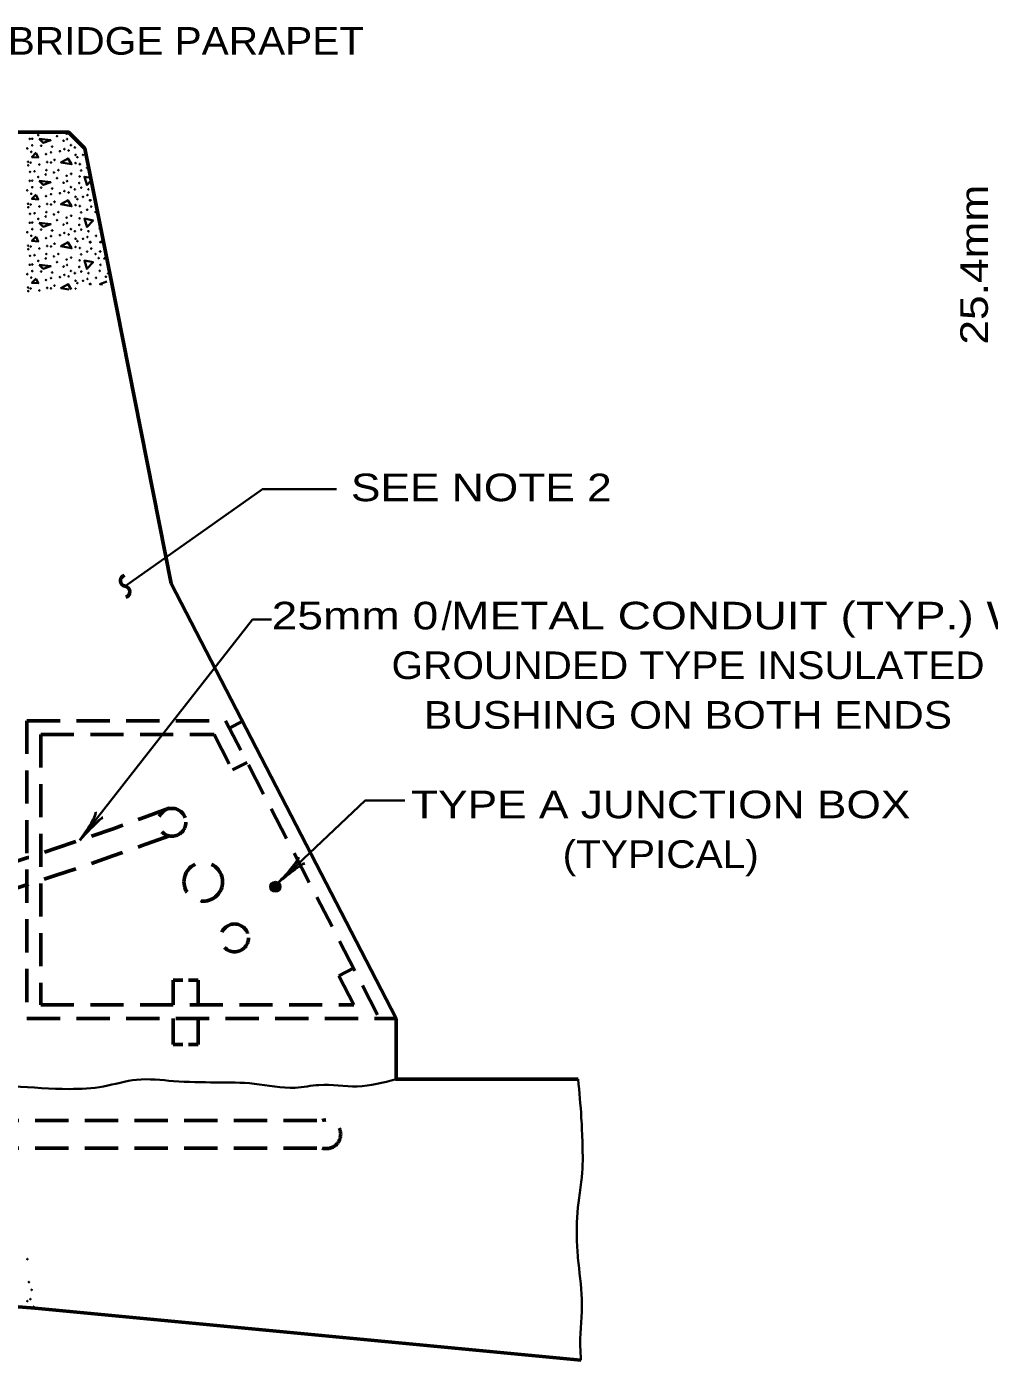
# Model space of a CAD drawing. Extents: x -35 to 821, y -23 to 522.
# Drawn here: x 406.3 to 511, y 94.3 to 239.3 of the extents above; entities that cross this region are included whole.
import ezdxf
from ezdxf.enums import TextEntityAlignment as Align

# ---------------------------------------------------------------- set-up
doc = ezdxf.new("R2010")
doc.units = 0
doc.header["$LTSCALE"] = 1.2
doc.linetypes.add('MEDIUM_DASHED', pattern=[4.5, 3, -1.5])
doc.layers.add('1', color=7, linetype='Continuous', lineweight=35)

msp = doc.modelspace()

# ---------------------------------------------------------------- hatches: boundary and pattern name
at = {"layer": '1'}
msp.add_hatch(color=256, dxfattribs=at).paths.add_polyline_path([(433.954, 145.752, 1), (432.754, 145.752, 1)])

# ---------------------------------------------------------------- linework, layer by layer
for p, q in [((413.331, 222.565), (412.859, 222.059)), ((411.148, 210.72), (410.771, 211.307)), ((406.92, 99.932), (406.947, 100.125)), ((406.995, 100.101), (407.181, 99.995))]:
    msp.add_line(p, q, dxfattribs=at)
at = {"layer": '1', "lineweight": 53}
for p, q in [((415.449, 211.896), (422.033, 178.739)), ((422.033, 178.739), (446.485, 131.414)), ((428.358, 163.014), (429.778, 163.748)), ((428.686, 158.456), (430.286, 159.283)), ((440.254, 136.068), (441.853, 136.894)), ((422.245, 132.914), (422.245, 135.614)), ((422.245, 135.614), (423.295, 135.614)), ((423.895, 135.614), (424.945, 135.614)), ((424.945, 132.914), (424.945, 135.614)), ((422.245, 131.414), (422.245, 128.599)), ((424.945, 131.414), (424.945, 128.599)), ((422.245, 128.599), (423.295, 128.599)), ((423.895, 128.599), (424.945, 128.599)), ((404.966, 100.123), (407.192, 99.912)), ((407.192, 99.912), (466.585, 94.257))]:
    msp.add_line(p, q, dxfattribs=at)
at = {"layer": '1', "linetype": 'MEDIUM_DASHED', "lineweight": 53}
for p, q in [((406.345, 163.814), (406.345, 131.414)), ((406.345, 163.814), (427.945, 163.814)), ((427.945, 163.814), (444.685, 131.414)), ((407.845, 162.314), (407.845, 132.914)), ((407.845, 162.314), (426.694, 162.314)), ((426.694, 162.314), (428.686, 158.456)), ((440.254, 136.068), (441.883, 132.914)), ((407.845, 132.914), (441.883, 132.914)), ((406.345, 131.414), (446.485, 131.414)), ((374.845, 120.328), (438.445, 120.328)), ((374.845, 117.341), (438.445, 117.341))]:
    msp.add_line(p, q, dxfattribs=at)
at = {"layer": '1', "lineweight": 53}
for points in [[(400.045, 227.82), (410.845, 227.82), (412.644, 226.02), (415.449, 211.896)], [(466.285, 124.814), (446.485, 124.814), (446.485, 131.414)]]:
    msp.add_lwpolyline(points, dxfattribs=at)
at = {"layer": '1'}
for points in [[(407.675, 227.075), (408.923, 226.931), (408.107, 226.643)], [(407.675, 222.515), (408.923, 222.371), (408.107, 222.083)], [(407.675, 217.955), (408.923, 217.811), (408.107, 217.523)], [(407.675, 213.395), (408.923, 213.251), (408.107, 212.963)]]:
    msp.add_lwpolyline(points, close=True, dxfattribs=at)
for points in [[(407.339, 225.587), (406.883, 225.107), (407.579, 225.059), (407.339, 225.539)], [(410.819, 224.963), (410.027, 224.531), (411.203, 224.315), (410.771, 224.987)], [(412.883, 222.011), (412.595, 222.971), (413.278, 222.831)], [(407.339, 221.027), (406.883, 220.547), (407.579, 220.499), (407.339, 220.979)], [(410.819, 220.403), (410.027, 219.971), (411.203, 219.755), (410.771, 220.427)], [(412.883, 217.451), (412.595, 218.411), (413.531, 218.219), (412.859, 217.499)], [(407.339, 216.467), (406.883, 215.987), (407.579, 215.939), (407.339, 216.419)], [(410.819, 215.843), (410.027, 215.411), (411.203, 215.195), (410.771, 215.867)], [(414.636, 215.989), (414.275, 215.843), (414.675, 215.797)], [(412.883, 212.891), (412.595, 213.851), (413.531, 213.659), (412.859, 212.939)], [(407.339, 211.907), (406.883, 211.427), (407.579, 211.379), (407.339, 211.859)], [(410.819, 211.283), (410.027, 210.851), (410.883, 210.694)], [(415.031, 211.589), (414.275, 211.283), (414.567, 211.249)], [(417.016, 178.427), (431.949, 189.003), (440.009, 189.003)], [(412.093, 150.812), (430.874, 174.812), (432.95, 174.812)], [(433.709, 146.236), (443.126, 155.138), (447.425, 155.138)]]:
    msp.add_lwpolyline(points, dxfattribs=at)
for centre in [(408.384, 227.766), (406.65, 227.079), (406.921, 227.098), (406.921, 226.382), (407.573, 227.495), (407.891, 226.334), (409.084, 226.239), (409.609, 227.368), (410.324, 226.875), (410.658, 227.638), (410.706, 227.05), (411.12, 226.398), (412.249, 226.334), (406.371, 226.048), (406.81, 225.672), (408.416, 225.417), (408.957, 225.624), (409.338, 224.797), (409.927, 225.735), (410.404, 225.968), (410.881, 225.815), (411.549, 226.159), (411.628, 225.338), (411.819, 225.083), (412.44, 225.338), (406.467, 224.59), (406.482, 224.208), (406.673, 223.492), (406.746, 224.494), (407.175, 223.556), (407.684, 224.288), (408.448, 223.683), (408.543, 224.558), (408.957, 224.51), (409.275, 223.429), (409.752, 223.683), (411.628, 224.447), (412.09, 224.335), (412.233, 223.651), (412.885, 223.938), (406.65, 222.519), (406.921, 222.538), (407.573, 222.935), (408.384, 223.206), (409.609, 222.808), (410.324, 222.315), (410.658, 223.078), (410.706, 222.49), (411.151, 223.285), (412.026, 222.283), (412.074, 222.999), (406.371, 221.488), (406.81, 221.112), (406.921, 221.822), (407.891, 221.774), (408.416, 220.857), (408.957, 221.064), (409.084, 221.679), (409.927, 221.175), (410.404, 221.408), (410.881, 221.255), (411.12, 221.838), (411.549, 221.599), (411.628, 220.778), (411.819, 220.523), (412.249, 221.774), (412.44, 220.778), (412.917, 220.969), (413.028, 221.599), (413.187, 220.412), (413.251, 220.412), (406.467, 220.03), (406.482, 219.648), (406.746, 219.934), (407.175, 218.996), (407.684, 219.728), (408.448, 219.123), (408.543, 219.998), (408.957, 219.95), (409.338, 220.237), (409.752, 219.123), (411.628, 219.887), (412.09, 219.775), (412.233, 219.091), (412.885, 219.378), (413.33, 219.712), (413.807, 219.123), (406.65, 217.959), (406.673, 218.932), (406.921, 217.978), (407.573, 218.375), (408.384, 218.646), (409.275, 218.869), (409.609, 218.248), (410.324, 217.755), (410.658, 218.518), (410.706, 217.93), (411.151, 218.725), (412.026, 217.723), (412.074, 218.439), (406.371, 216.928), (406.81, 216.552), (406.921, 217.262), (407.891, 217.214), (408.416, 216.297), (408.957, 216.504), (409.084, 217.119), (409.927, 216.615), (410.404, 216.848), (410.881, 216.695), (411.12, 217.278), (411.549, 217.039), (411.628, 216.218), (412.249, 217.214), (412.44, 216.218), (412.917, 216.409), (413.028, 217.039), (413.855, 216.536), (414.253, 217.294), (406.467, 215.47), (406.482, 215.088), (406.746, 215.374), (407.684, 215.168), (408.543, 215.438), (408.957, 215.39), (409.338, 215.677), (411.628, 215.327), (411.819, 215.963), (412.09, 215.215), (412.885, 214.818), (413.187, 215.852), (413.251, 215.852), (413.33, 215.152), (414.3, 214.834), (406.65, 213.399), (406.673, 214.372), (406.921, 213.418), (407.175, 214.436), (407.573, 213.815), (408.384, 214.086), (408.448, 214.563), (409.275, 214.309), (409.609, 213.688), (409.752, 214.563), (410.324, 213.195), (410.658, 213.958), (410.706, 213.37), (411.151, 214.165), (412.026, 213.163), (412.074, 213.879), (412.233, 214.531), (413.807, 214.563), (414.141, 214.118), (414.332, 213.386), (414.761, 214.086), (406.371, 212.368), (406.81, 211.992), (406.921, 212.702), (407.891, 212.654), (408.416, 211.737), (408.957, 211.944), (409.084, 212.559), (409.927, 212.055), (410.404, 212.288), (410.881, 212.135), (411.12, 212.718), (411.549, 212.479), (412.249, 212.654), (412.917, 211.849), (413.028, 212.479), (413.855, 211.976), (414.253, 212.734), (414.921, 212.087), (415.175, 212.463), (406.467, 210.91), (406.482, 210.528), (406.746, 210.814), (407.684, 210.608), (408.543, 210.878), (408.957, 210.83), (409.338, 211.117), (411.628, 211.658), (411.819, 211.403), (412.44, 211.658), (413.187, 211.292), (413.251, 211.292), (406.379, 105.259), (406.554, 102.761), (406.856, 101.924), (406.379, 100.699), (406.713, 100.906)]:
    msp.add_circle(centre, 0.0318, dxfattribs=at)
at = {"layer": '1', "linetype": 'MEDIUM_DASHED', "lineweight": 53}
for centre, radius in [((422.106, 152.769), 1.513), ((425.514, 146.287), 2.1), ((428.912, 140.193), 1.513)]:
    msp.add_circle(centre, radius, dxfattribs=at)
at = {"layer": '1', "lineweight": 13}
msp.add_circle((433.354, 145.752), 0.6, dxfattribs=at)
at = {"layer": '1'}
msp.add_arc((411.628, 210.767), 0.0318, 30.26479, 165.70427, dxfattribs=at)
at = {"layer": '1', "lineweight": 53}
for centre, start, end in [((417.12, 179.034), 105.71531, 260.28469), ((416.912, 177.821), 285.71531, 80.28469)]:
    msp.add_arc(centre, 0.615, start, end, dxfattribs=at)
at = {"layer": '1', "linetype": 'MEDIUM_DASHED', "lineweight": 53}
for centre, radius, start, end in [((285.088, 520.901), 391.275, 282.8105, 290.45715), ((272.403, 560.369), 435.509, 283.19898, 290.06715), ((438.896, 118.834), 1.56, 253.19227, 106.80773)]:
    msp.add_arc(centre, radius, start, end, dxfattribs=at)
at = {"layer": '1', "lineweight": 40}
for centre, major_axis, ratio, start_param, end_param in [((412.639, 152.047), (-1.173, -1.803), 0.122415, 0.8963533, 3.1415927), ((413.121, 151.714), (1.465, 1.53), 0.07063, 6.2823074, 8.5597026), ((434.433, 147.376), (-1.428, -1.608), 0.122415, 0.8963533, 3.1415927), ((434.861, 146.975), (-1.676, -1.295), 0.07063, 3.1407148, 5.41811)]:
    msp.add_ellipse(centre, major_axis=major_axis, ratio=ratio, start_param=start_param, end_param=end_param, dxfattribs=at)
at = {"layer": '1'}
for points in [[(381.445, 124.92), (384.645, 124.911), (388.668, 124.336), (393.697, 124.048), (397.145, 124.336), (401.456, 124.192), (404.904, 124.048), (410.939, 123.761), (414.675, 124.048), (418.267, 124.767), (422.29, 124.623), (426.888, 124.48), (431.055, 124.336), (435.509, 123.905), (438.096, 124.192), (442.262, 124.048), (446.485, 124.814)], [(466.285, 124.814), (466.62, 120.637), (466.742, 117.834), (466.681, 114.178), (466.377, 111.924), (466.133, 107.659), (466.255, 105.404), (466.681, 100.895), (466.62, 98.519), (466.498, 96.143), (466.585, 94.257)]]:
    msp.add_spline(points, degree=3, dxfattribs=at)

# ---------------------------------------------------------------- texts
for s, width, p in [('BRIDGE PARAPET', 1.1, (404.254, 236.24)), ('SEE NOTE 2', 1.2, (441.569, 187.681))]:
    msp.add_text(s, height=3, dxfattribs=dict(at, width=width)).set_placement(p)
at = {"layer": '1', "width": 1.2}
msp.add_text('25.4mm', height=3, rotation=90, dxfattribs=at).set_placement((510.828, 204.708))
at = {"layer": '1'}
for s, width, p in [('25mm 0 METAL CONDUIT (TYP.) WITH', 1.25, (478.224, 173.743)), ('GROUNDED TYPE INSULATED', 1.1, (478.224, 168.343)), ('BUSHING ON BOTH ENDS', 1.15, (478.224, 162.943)), ('TYPE A JUNCTION BOX', 1.2, (475.252, 153.205)), ('(TYPICAL)', 1.1, (475.252, 147.805))]:
    msp.add_text(s, height=3, dxfattribs=dict(at, width=width)).set_placement(p, align=Align.CENTER)
msp.add_text('/', height=3, dxfattribs=at).set_placement((451.427, 173.694))

doc.saveas('drawing.dxf')
